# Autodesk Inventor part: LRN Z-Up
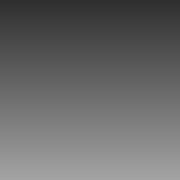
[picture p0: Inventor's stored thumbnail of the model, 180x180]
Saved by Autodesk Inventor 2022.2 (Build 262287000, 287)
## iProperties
Created: 2023-03
Part Number: LRN Z-Up
Material: Generic
Document SubType Name: Modeling
Designer: g4ecdbje
Density: 1 g/cm^3
Appearance: Default
Author: g4ecdbje
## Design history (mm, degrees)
